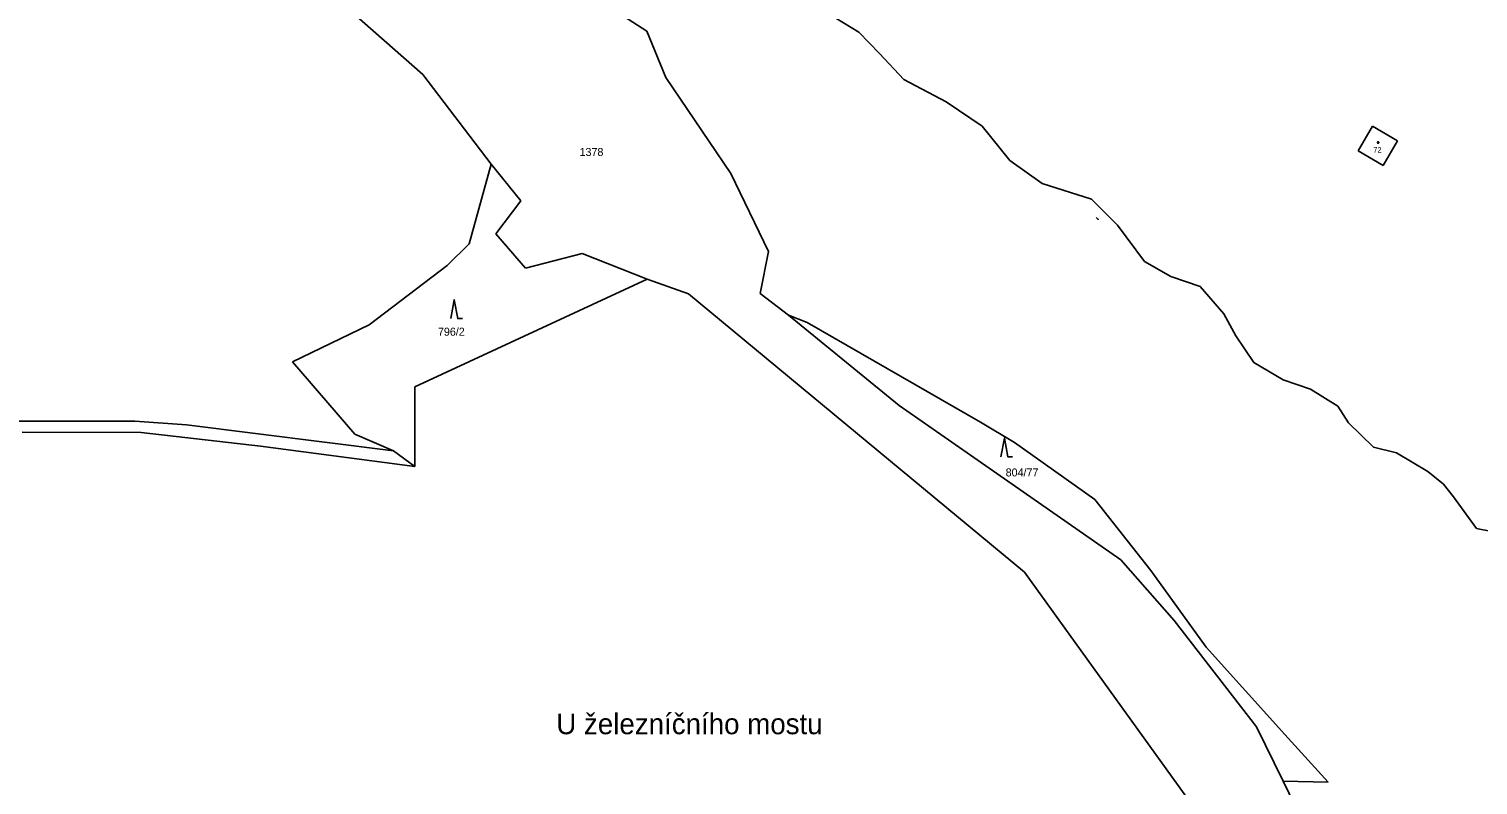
# Model space of a CAD drawing. Extents: x -845995 to -842497, y -1063614 to -1059680.
# Drawn here: x -843659.2 to -843351.4, y -1062001.9 to -1061841.4 of the extents above; entities that cross this region are included whole.
import ezdxf

# ---------------------------------------------------------------- set-up
doc = ezdxf.new("R2010")
doc.units = 0
for name, color, linetype in [('KN_HRANICE', 7, 'Continuous'), ('KN_KULTURY', 7, 'Continuous'), ('KN_PARCELY', 7, 'Continuous'), ('KN_SLUCKY', 7, 'Continuous'), ('KN_STAVEBNI', 7, 'Continuous')]:
    doc.layers.add(name, color=color, linetype=linetype)

# ---------------------------------------------------------------- blocks, each defined once
blk = doc.blocks.new('308')
blk.add_lwpolyline([(-0.75, 0), (0, 4), (0.75, 0), (1.75, 0)])
blk = doc.blocks.new('1060')
blk.add_line((-0.3, 0), (0.3, 0))
blk.add_lwpolyline([(0.18, 0.04), (0.3, 0), (0.18, -0.04)])
blk = doc.blocks.new('402')
blk.add_lwpolyline([(0.09, 0.15), (0.18, 0), (0.09, -0.15), (-0.09, -0.15), (-0.18, 0), (-0.09, 0.15), (0.09, 0.15)])

msp = doc.modelspace()

# ---------------------------------------------------------------- linework, layer by layer
at = {"layer": 'KN_HRANICE'}
for p, q in [((-843659.13, -1061777.56), (-843575.5, -1061851.1)), ((-843527.93, -1061841.9), (-843532.89, -1061838.69)), ((-843523.95, -1061851.73), (-843527.93, -1061841.9)), ((-843575.5, -1061851.1), (-843561, -1061870.14)), ((-843510.14, -1061872.13), (-843523.95, -1061851.73)), ((-843373.8, -1061862.07), (-843376.87, -1061867.27)), ((-843368.5, -1061865.2), (-843373.8, -1061862.07)), ((-843376.87, -1061867.27), (-843371.59, -1061870.39)), ((-843371.59, -1061870.39), (-843368.5, -1061865.2)), ((-843561, -1061870.14), (-843565.72, -1061887.02)), ((-843561, -1061870.14), (-843554.72, -1061877.9)), ((-843502.1, -1061888.66), (-843510.14, -1061872.13)), ((-843554.72, -1061877.9), (-843560.02, -1061884.93)), ((-843560.02, -1061884.93), (-843553.73, -1061892.2)), ((-843565.72, -1061887.02), (-843570.36, -1061891.66)), ((-843553.73, -1061892.2), (-843541.66, -1061889.12)), ((-843541.66, -1061889.12), (-843527.86, -1061894.54)), ((-843503.85, -1061897.57), (-843502.1, -1061888.66)), ((-843570.36, -1061891.66), (-843586.92, -1061904.25)), ((-843577.25, -1061917.38), (-843527.86, -1061894.54)), ((-843527.86, -1061894.54), (-843519.11, -1061897.62)), ((-843519.11, -1061897.62), (-843447.74, -1061956.71)), ((-843497.88, -1061902.17), (-843503.85, -1061897.57)), ((-843586.92, -1061904.25), (-843603.22, -1061912.07)), ((-843474.38, -1061921.33), (-843497.88, -1061902.17)), ((-843497.88, -1061902.17), (-843493.89, -1061903.71)), ((-843493.89, -1061903.71), (-843457.08, -1061924.86)), ((-843603.22, -1061912.07), (-843589.97, -1061927.45)), ((-843577.26, -1061934.32), (-843577.25, -1061917.38)), ((-843427.27, -1061954.14), (-843474.38, -1061921.33)), ((-843636.67, -1061924.71), (-843677.25, -1061924.62)), ((-843625.73, -1061925.47), (-843636.67, -1061924.71)), ((-843581.73, -1061930.99), (-843625.73, -1061925.47)), ((-843457.08, -1061924.86), (-843449.87, -1061929.22)), ((-843660.62, -1061927.01), (-843635.34, -1061927.1)), ((-843635.34, -1061927.1), (-843610.04, -1061929.96)), ((-843589.97, -1061927.45), (-843581.73, -1061930.99)), ((-843449.87, -1061929.22), (-843432.83, -1061941.28)), ((-843610.04, -1061929.96), (-843577.26, -1061934.32)), ((-843577.26, -1061934.32), (-843581.73, -1061930.99)), ((-843432.83, -1061941.28), (-843420.93, -1061956.38)), ((-843415.95, -1061966.96), (-843427.27, -1061954.14)), ((-843447.74, -1061956.71), (-843410.34, -1062008.61)), ((-843420.93, -1061956.38), (-843409.12, -1061972.68)), ((-843398.44, -1061989.53), (-843415.95, -1061966.96)), ((-843409.12, -1061972.68), (-843392.46, -1061991.22)), ((-843392.79, -1062001.1), (-843398.44, -1061989.53)), ((-843392.46, -1061991.22), (-843383.26, -1062001.29)), ((-843357.43, -1062073.51), (-843392.79, -1062001.1)), ((-843383.26, -1062001.29), (-843392.79, -1062001.1))]:
    msp.add_line(p, q, dxfattribs=at)
at = {"layer": 'KN_SLUCKY'}
for p, q in [((-843489.41, -1061838.18), (-843482.93, -1061842.1)), ((-843482.93, -1061842.1), (-843478.51, -1061846.67)), ((-843478.51, -1061846.67), (-843473.34, -1061852.15)), ((-843473.34, -1061852.15), (-843464.36, -1061856.87)), ((-843464.36, -1061856.87), (-843456.76, -1061862.05)), ((-843456.76, -1061862.05), (-843450.82, -1061869.35)), ((-843450.82, -1061869.35), (-843443.98, -1061874.22)), ((-843443.98, -1061874.22), (-843433.48, -1061877.57)), ((-843433.48, -1061877.57), (-843428, -1061883.05)), ((-843428, -1061883.05), (-843422.22, -1061890.82)), ((-843422.22, -1061890.82), (-843416.67, -1061893.96)), ((-843416.67, -1061893.96), (-843410.43, -1061896.09)), ((-843410.43, -1061896.09), (-843405.41, -1061901.87)), ((-843405.41, -1061901.87), (-843402.83, -1061906.59)), ((-843402.83, -1061906.59), (-843399.02, -1061912.22)), ((-843399.02, -1061912.22), (-843392.78, -1061915.88)), ((-843392.78, -1061915.88), (-843387, -1061917.86)), ((-843387, -1061917.86), (-843381.22, -1061921.51)), ((-843381.22, -1061921.51), (-843378.94, -1061925.01)), ((-843378.94, -1061925.01), (-843373.61, -1061930.19)), ((-843373.61, -1061930.19), (-843368.74, -1061931.4)), ((-843368.74, -1061931.4), (-843362.05, -1061935.36)), ((-843362.05, -1061935.36), (-843358.74, -1061938.03)), ((-843358.74, -1061938.03), (-843356.61, -1061940.77)), ((-843356.61, -1061940.77), (-843351.74, -1061947.46)), ((-843351.74, -1061947.46), (-843344.89, -1061948.83))]:
    msp.add_line(p, q, dxfattribs=at)
at = {"layer": 'KN_STAVEBNI'}
for p, q in [((-843373.8, -1061862.07), (-843376.87, -1061867.27)), ((-843368.5, -1061865.2), (-843373.8, -1061862.07)), ((-843376.87, -1061867.27), (-843371.59, -1061870.39)), ((-843371.59, -1061870.39), (-843368.5, -1061865.2))]:
    msp.add_line(p, q, dxfattribs=at)

# ---------------------------------------------------------------- block references
at = {"layer": 'KN_KULTURY'}
for name, p in [('402', (-843372.61, -1061865.53)), ('308', (-843568.85, -1061902.89)), ('308', (-843452.02, -1061932.28))]:
    msp.add_blockref(name, p, dxfattribs=at)
at = {"layer": 'KN_PARCELY', "rotation": -46.07642400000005}
msp.add_blockref('1060', (-843432.29, -1061881.63), dxfattribs=at)

# ---------------------------------------------------------------- texts
at = {"layer": 'KN_PARCELY'}
for s, height, p in [('1378', 1.7, (-843542.24, -1061868.39)), ('72', 1.14, (-843373.64, -1061867.65)), ('796/2', 1.7, (-843572.32, -1061906.54)), ('804/77', 1.7, (-843451.74, -1061936.41)), ('U železníčního mostu', 4.4, (-843547.19, -1061991.13))]:
    msp.add_text(s, height=height, dxfattribs=at).set_placement(p)

doc.saveas('drawing.dxf')
